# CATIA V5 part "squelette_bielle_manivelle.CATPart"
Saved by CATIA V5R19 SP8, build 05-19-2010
Part number: squelette_bielle_manivelle
Publications: "Droite.1", "Droite.2", "Plan.1", "Plan.3"
Bounding box of the stored display mesh (mm): x 83 to 83, y 0.085 to 30.629, z 64.516 to 66.284
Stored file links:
  G:\EU_thinkMotion\CFAO_2010\MMS_groupe3\MMS_groupe3\A reprendre\amenand\amenand\squelette_bielle_manivelle.CATPart
  F:\thinkmotion CFAO v12.1\essuie_glace.CATProduct
  G:\EU_thinkMotion\CFAO_2010\MMS_groupe3\MMS_groupe3\A reprendre\amenand\amenand\squelette_bati.CATPart
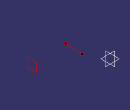
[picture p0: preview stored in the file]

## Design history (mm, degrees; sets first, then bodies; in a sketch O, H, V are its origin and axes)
Line1: type PtPt, FirstPoint Point1, SecondPoint Point2
Set1
  Plane1: linked copy from another document
  Point1: linked copy from another document
  Point2: linked copy from another document
Body1 (main body)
